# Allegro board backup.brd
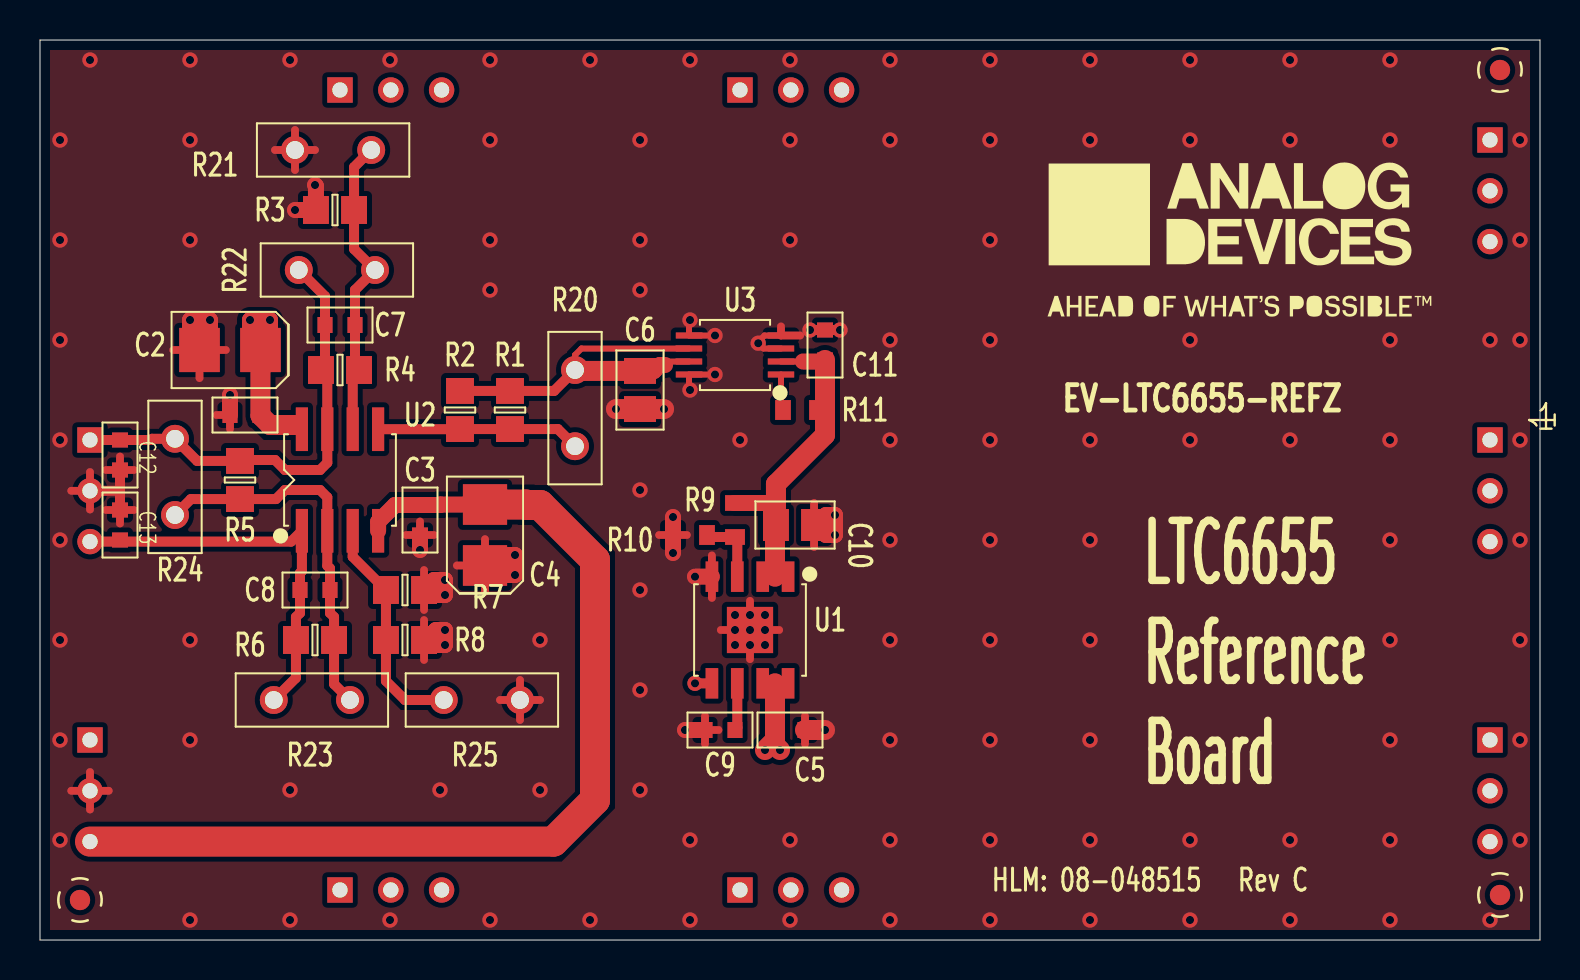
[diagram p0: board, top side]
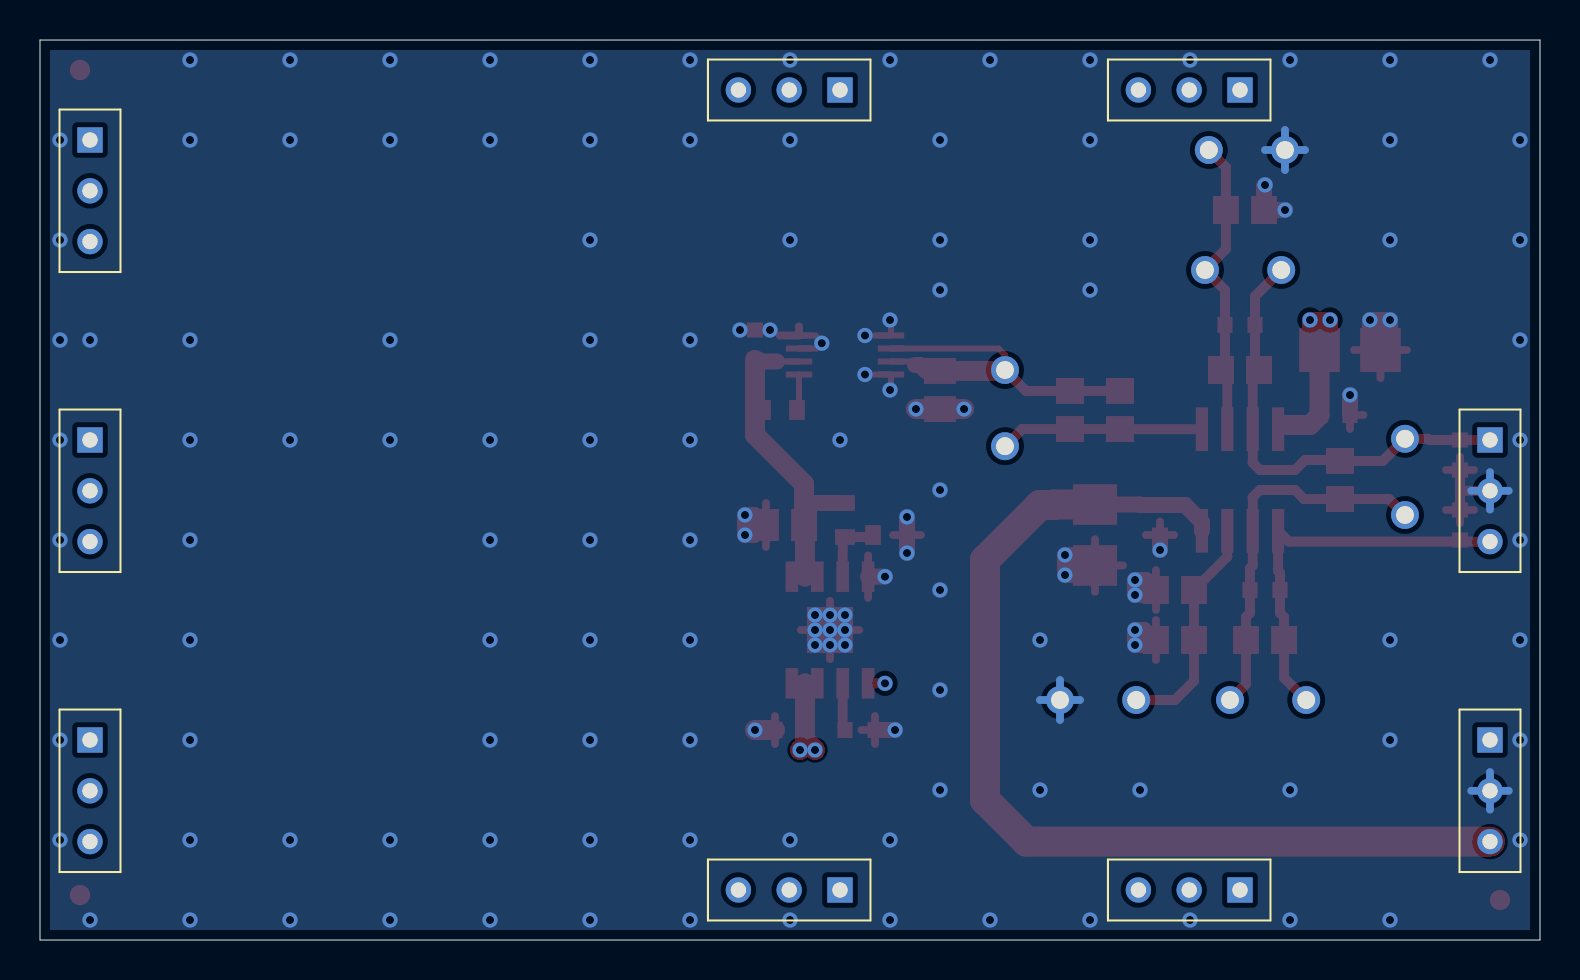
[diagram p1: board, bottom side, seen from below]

Outline 75 x 45 mm; copper layers: TOP, LAYER2, LAYER3, BOTTOM. Coordinates in mm from the lower left corner of the outline.
Outline path: 0,45 0,0 75,0 75,45 0,45

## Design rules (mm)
constraint set DEFAULT: min track width 0.19

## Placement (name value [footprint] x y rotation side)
C1  0.1UF  [C0603]  10.25 26.25 0 top
C2  10uF  [C3528]  9.5 29.5 180 top
C3  0.1UF  [C0603]  19 21 270 top
C4  10uF  [C3528]  22.25 20.25 90 top
C5  1uF  [C0603]  37.5 10.5 0 top
C6  10UF  [C0805H53]  30 27.5 270 top
C7  0.1UF  [C0603]  15 30.75 180 top
C8  0.1UF  [C0603]  13.75 17.5 180 top
C9  10000pF  [C0603]  34 10.5 180 top
C10  2.2UF  [C0805H53]  37.75 20.75 0 top
C11  0.1UF  [C0603]  39.25 29.75 90 top
C12  1UF  [C0603]  4 24.25 270 top
C13  1UF  [C0603]  4 20.75 270 top
J1  350-10-103-00-006000  [CNTHMHDR1X3L300W100H284]  2.5 10 270 bottom
J2  350-10-103-00-006000  [CNTHMHDR1X3L300W100H284]  35 42.5 0 bottom
J3  350-10-103-00-006000  [CNTHMHDR1X3L300W100H284]  15 42.5 0 bottom
J4  310-13-103-41-001000  [CNTHFHDR1X3L300W100H165]  2.5 25 270 bottom
J5  310-13-103-41-001000  [CNTHFHDR1X3L300W100H165]  72.5 40 270 bottom
J6  310-13-103-41-001000  [CNTHFHDR1X3L300W100H165]  15 2.5 0 bottom
J7  350-10-103-00-006000  [CNTHMHDR1X3L300W100H284]  35 2.5 0 bottom
J8  350-10-103-00-006000  [CNTHMHDR1X3L300W100H284]  72.5 10 270 bottom
J9  350-10-103-00-006000  [CNTHMHDR1X3L300W100H284]  72.5 25 270 bottom
NOREF  -  []  0 45 0 top
NOREF#2  -  [unnamed#2]  2 2 0 top
NOREF#3  -  []  -100 -95 0 top
NOREF#4  -  []  60 35 0 top
NOREF#5  -  []  36 14 0 top
NOREF#6  -  []  0 0 90 top
NOREF#7  -  [unnamed#2]  73 2.25 0 top
NOREF#8  -  []  -105 -95 0 top
NOREF#9  -  [unnamed#2]  73 43.5 0 top
NOREF#10  -  []  36.75 -16.25 0 top
R1  10K  [R0805]  23.5 26.5 270 top
R2  10K  [R0805]  21 26.5 270 top
R3  10K  [R0805]  14.75 36.5 0 top
R4  10K  [R0805]  15 28.5 180 top
R5  10K  [R0805]  10 23 90 top
R6  10K  [R0805]  13.75 15 180 top
R7  10K  [R0805]  18.25 17.5 180 top
R8  10K  [R0805]  18.25 15 180 top
R9  100K  [R0603]  34.75 21 270 top
R10  10K  [R0603]  32.5 20.25 180 top
R11  10K  [R0603]  38 26.5 180 top
R20  10K  [RRADTH150L300H336W105LD25]  26.75 28.5 270 top
R21  10K  [RRADTH150L300H336W105LD25]  12.75 39.5 0 top
R22  10K  [RRADTH150L300H336W105LD25]  16.75 33.5 180 top
R23  10K  [RRADTH150L300H336W105LD25]  15.5 12 180 top
R24  10K  [RRADTH150L300H336W105LD25]  6.75 21.25 90 top
R25  10K  [RRADTH150L300H336W105LD25]  24 12 180 top
U1  ADP7118ARDZ  [SO8NB-PAD2_3X2_3]  35.5 15.5 180 top
U2  ADA4077-2BRZ  [SO8]  15 23 0 top
U3  LTC6655BHMS8-5#PBF  [MSOP8]  34.75 29.25 90 top

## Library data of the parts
C1 C3 C7 C8 C11 = CAP: User Part Number: UPN; Tolerance: 10; alternate symbols: (); part number: CAP_SM-0.1UF,25V,10,E007204,C0603; tolerance: 10
C2 C4 = CAPP: User Part Number: UPN; Tolerance: N/A; alternate symbols: (); part number: CAPP_SM-10UF,N/A,N/A,E000695,C3528; tolerance: N/A
C5 = CAP: User Part Number: UPN; Tolerance: 10; alternate symbols: (); part number: CAP_SM-1UF,16V,10,E020596,C0603; tolerance: 10
C6 = CAP: Tolerance: 10; User Part Number: UPN; alternate symbols: (); part number: CAP_SM-10UF,10V,10,E023214,C0805H53; tolerance: 10
C9 = CAP: User Part Number: UPN; Tolerance: 10; alternate symbols: (); part number: CAP_SM-10000PF,50V,10,E015914,C0603; tolerance: 10
C10 = CAP: Tolerance: 10; User Part Number: UPN; alternate symbols: (); part number: CAP_SM-2.2UF,25V,10,E025703,C0805H53; tolerance: 10
C12 C13 = CAP: User Part Number: UPN; Tolerance: 10; alternate symbols: (); part number: CAP_SM-1UF,10V,10,E033698,C0603; tolerance: 10
J1-J3 J7-J9 = CN3P: User Part Number: UPN; Tolerance: N/A; alternate symbols: (); part number: CN3P_TH-350-10-103-00-006000,E027762,CNTHMHDR1X3L300W100H284; tolerance: N/A
J4-J6 = CN3P: User Part Number: UPN; Tolerance: N/A; alternate symbols: (); part number: CN3P_TH-310-13-103-41-001000,E027752,CNTHFHDR1X3L300W100H165; tolerance: N/A
R1-R8 = RES: User Part Number: UPN; Tolerance: 0.1; alternate symbols: (R0805L); part number: RES_SM-10K,E003806,1/8W,0.1,R0805; tolerance: 0.1
R9 = RES: User Part Number: UPN; Tolerance: 1; alternate symbols: (R0603L); part number: RES_SM-100K,E010279,1/10W,1,R0603; tolerance: 1
R10 R11 = RES: User Part Number: UPN; Tolerance: 1; alternate symbols: (R0603L); part number: RES_SM-10K,E003671,1/10W,1,R0603; tolerance: 1
R20-R25 = RES: Tolerance: 0.005; User Part Number: UPN; alternate symbols: (); part number: RES_TH-10K,E018578,6/10W,0.005,RRADTH150L300H336W105LD25; tolerance: 0.005
U1 = ADP7118_V3: Tolerance: N/A; User Part Number: UPN; alternate symbols: (); part number: ADP7118_V3_SM-ADP7118ARDZ,E020780,SO8NB-PAD2_3X2_3; tolerance: N/A
U2 = ADA4077_2: User Part Number: UPN; Tolerance: N/A; alternate symbols: (); part number: ADA4077_2_SM-ADA4077-2BRZ,E018506,SO8; tolerance: N/A
U3 = LINLTC6655: Tolerance: N/A; User Part Number: UPN; alternate symbols: (); part number: LINLTC6655_SM-LTC6655BHMS8-5#PBF,E020815,MSOP8; tolerance: N/A

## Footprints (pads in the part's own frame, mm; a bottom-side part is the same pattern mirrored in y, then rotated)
C0603
  rect 0.75x0.8 smd: 1(-0.75,0) 2(0.75,0)
C0805H53
  rect 1.295x1.6 smd: 1(-0.953,0) 2(0.953,0)
C3528
  rect 2.032x2.21 smd: N(1.524,0) P(-1.524,0)
CNTHFHDR1X3L300W100H165
  rect 1.27x1.27 hole 0.762: 1(0,0)
  round 1.27 hole 0.762: 2(2.54,0) 3(5.08,0)
CNTHMHDR1X3L300W100H284
  rect 1.27x1.27 hole 0.762: 1(0,0)
  round 1.27 hole 0.762: 2(2.54,0) 3(5.08,0)
MSOP8
  rect 0.305x1.321 smd: 1(-0.975,-2.3) 2(-0.325,-2.3) 3(0.325,-2.3) 4(0.975,-2.3) 5(0.975,2.3) 6(0.325,2.3) 7(-0.325,2.3) 8(-0.975,2.3)
R0603
  rect 0.787x0.991 smd: 1(-0.85,0) 2(0.85,0)
R0805
  rect 1.295x1.397 smd: 1(-0.953,0) 2(0.953,0)
RRADTH150L300H336W105LD25
  round 1.397 hole 0.889: 1(0,0) 2(3.81,0)
SO8
  rect 0.61x2.184 smd: 1(-1.905,-2.54) 2(-0.635,-2.54) 3(0.635,-2.54) 4(1.905,-2.54) 5(1.905,2.54) 6(0.635,2.54) 7(-0.635,2.54) 8(-1.905,2.54)
SO8NB-PAD2_3X2_3
  rect 0.635x1.524 smd: 1(-1.905,-2.667) 2(-0.635,-2.667) 3(0.635,-2.667) 4(1.905,-2.667) 5(1.905,2.667) 6(0.635,2.667) 7(-0.635,2.667) 8(-1.905,2.667)
  rect 2.311x2.311 smd: PAD(0,0)
unnamed#2
  round 1.016 smd: (0,0)

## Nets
AGND: C1.1 C2.N(N2) C3.2(N2) C4.P C5.2(N2) C6.2(N2) C9.2(N2) C10.2(N2) C11.2(N2) C12.2(N2) C13.1 J1.2 J4.2 R3.1 R7.1 R8.1 R10.2(N2) R21.1 R25.1 U1.4 U1.PAD U3.3 U3.4 U3.5 U3.8
VDD: C1.2(N2) C2.P C5.1 J1.1 U1.5 U1.7 U1.8 U2.8
VSS: C3.1 C4.N(N2) J1.3(N3) U2.4(V-)
UNNAMED_2_ADA40772_I74_: C7.1 R3.2(N2) R4.1 R21.2(N2) R22.1 U2.6
UNNAMED_2_ADA40772_I74__1: R1.2(N2) R2.2(N2) R20.2(N2) U2.5
UNNAMED_2_ADA40772_I75_: C8.1 R5.1 R6.1 R23.1 R24.1 U2.2
UNNAMED_2_ADA40772_I75__1: R7.2(N2) R8.2(N2) R25.2(N2) U2.3
UNNAMED_2_ADP7118V3_I79_SENSE: R9.2(N2) R10.1 U1.3
UNNAMED_2_ADP7118V3_I79_SS: C9.1 U1.6
UNNAMED_2_ADP7118V3_I79_VOUT1: C10.1 C11.1 R9.1 R11.1 U1.1 U1.2(VOUT2) U3.2
UNNAMED_2_CAP_I32_N1: C6.1 R1.1 R2.1 R20.1 U3.6(VOUT_S) U3.7
UNNAMED_2_LINLTC6655_I78_SHDNN: R11.2(N2) U3.1
VREFN: C8.2(N2) C13.2(N2) J4.3(N3) R6.2(N2) R23.2(N2) U2.1
VREFP: C7.2(N2) C12.1 J4.1 R4.2(N2) R5.2(N2) R22.2(N2) R24.2(N2) U2.7

Pads without a net: J2 1 2 3; J3 1 2 3; J5 1 2 3; J6 1 2 3; J7 1 2 3; J8 1 2 3; J9 1 2 3

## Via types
v1: diameter 0.762, hole 0.406, TOP to BOTTOM, 145 vias

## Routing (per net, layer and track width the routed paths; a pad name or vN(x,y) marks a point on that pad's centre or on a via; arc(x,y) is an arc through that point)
AGND: length 357.9
  TOP w0.3: v1(35.5,15.5) v1(34.75,16.25) ; v1(32.5,27.5) 32.45,27.55 U3.8 v1(33.75,28.27) ; U3.4 36.23,30.23 35.91,29.91 v1(35.91,29.84) 36.17,29.57 U3.3 ; v1(32.5,31) 32.45,30.95 U3.5 v1(33.75,30.23)
  TOP w0.39: J4.2 2.5,23.4 ; J4.2 2.5,21.52 ; J4.2 1.56,22.46 ; 38.7,21.85 C10.2 38.7,19.65 ; C13.1 4.7,21.5 ; C13.1 4,20.82 ; C13.1 3.3,21.5 ; C4.P 23.66,18.73 ; C4.P 22.25,17.41 ; C4.P 20.84,18.73 ; C4.P 22.25,20.04 ; R7.1 20.15,17.5 ; R7.1 19.2,16.5 ; R7.1 19.2,18.5 ; C9.2 33.93,10.5 ; C9.2 33.25,9.8 ; C9.2 33.25,11.2 ; 38.25,9.8 C5.2 38.25,11.2 ; 3.3,23.5 C12.2 ; C12.2 4,24.18 ; C12.2 4.7,23.5 ; 19.2,14 R8.1 19.2,16 ; 38.01,30.23 U3.4 37.05,30.68 ; R25.1 24,13 ; R25.1 25,12 ; R25.1 24,11 ; R25.1 23,12 ; 30.96,20.25 R10.2 32.34,20.25 ; 12.75,38.5 R21.1 ; R21.1 13.75,39.5 ; R21.1 11.75,39.5 ; R21.1 12.75,40.5 ; v1(35.5,15.5) 36.96,15.5 ; v1(35.5,15.5) 35.5,14.04 ; v1(35.5,15.5) 35.5,16.96 ; v1(35.5,15.5) 34.04,15.5 ; 1.56,7.46 J1.2 ; J1.2 3.44,7.46 ; J1.2 2.5,8.4 ; J1.2 2.5,6.52 ; 18.3,20.25 C3.2 ; C3.2 19,20.93 ; C3.2 19.7,20.25 ; 8.82,26.25 C1.1 9.5,25.55 ; 33.59,17.1 U1.4 33.59,19.23 ; 6.66,29.5 C2.N ; C2.N 9.29,29.5 ; C2.N 7.98,28.09
  TOP w0.5: 4,22.41 3.95,22.46 J4.2 ; 4,22.41 C12.2 ; 4,22.41 C13.1 ; v1(40,30.5) C11.2 v1(38.5,30.5)
  TOP w0.8: C10.2 39.25,20.75 ; 39.25,20.75 39.25,21.2 39.3,21.25 v1(39.75,21.25) v1(39.75,20.25) 39.3,20.25 39.25,20.3 39.25,20.75 ; C3.2 v1(19,19.5) ; R8.1 19.75,15 ; 19.75,15 19.75,15.45 19.8,15.5 v1(20.25,15.5) v1(20.25,14.75) 19.8,14.75 19.75,14.8 19.75,15 ; C2.N 7.98,30.48 ; 7.98,30.48 7.55,30.48 7.5,30.53 v1(7.5,31) v1(8.5,31) 8.5,30.53 8.45,30.48 7.98,30.48 ; C9.2 v1(32.25,10.5) ; C1.1 v1(9.5,27.25) ; v1(31.65,21.15) R10.2 v1(31.65,19.35) ; U1.4 v1(32.75,18.17) ; v1(12.75,36.5) R3.1 13.8,37.7 v1(13.75,37.75) ; 19.45,17.25 v1(20.25,17.25) v1(20.25,18) 19.7,18 R7.1 19.45,17.25 ; 22.77,19.25 C4.P 22.73,18.25 v1(23.75,18.25) v1(23.75,19.25) 22.77,19.25
  TOP w1: v1(28.8,26.55) C6.2 v1(31.2,26.55) ; C5.2 v1(39.25,10.5)
  LAYER2 w0.39: 1.56,22.46 J4.2 ; J4.2 2.5,21.52 ; J4.2 2.5,23.4 ; J4.2 3.44,22.46 ; R25.1 25,12 ; R25.1 24,11 ; R25.1 23,12 ; R25.1 24,13 ; 1.56,7.46 J1.2 ; J1.2 3.44,7.46 ; J1.2 2.5,8.4 ; J1.2 2.5,6.52 ; 11.75,39.5 R21.1 ; R21.1 12.75,38.5 ; R21.1 13.75,39.5 ; R21.1 12.75,40.5
  LAYER3 w1: v1(27.5,1) v1(22.5,1) v1(17.5,1) v1(12.5,1) v1(7.5,1) 1.05,1 1,1.05 v1(1,5) v1(1,10) v1(1,15) v1(1,20) v1(1,25) v1(1,30) v1(1,35) v1(1,40) 1,43.95 1.05,44 v1(2.5,44) v1(7.5,44) v1(12.5,44) v1(17.5,44) v1(22.5,44) v1(27.5,44) v1(32.5,44) v1(37.5,44) v1(42.5,44) v1(47.5,44) v1(52.5,44) v1(57.5,44) v1(62.5,44) v1(67.5,44) 73.95,44 74,43.95 v1(74,40) v1(74,35) v1(74,30) v1(74,25) v1(74,20) v1(74,15) v1(74,10) v1(74,5) 74,1.05 73.95,1 v1(72.5,1) v1(67.5,1) v1(62.5,1) v1(57.5,1) v1(52.5,1) v1(47.5,1) v1(42.5,1) v1(37.5,1) v1(32.5,1) v1(27.5,1)
  BOTTOM w0.39: 2.5,21.52 J4.2 ; J4.2 1.56,22.46 ; J4.2 2.5,23.4 ; J4.2 3.44,22.46 ; 2.5,6.52 J1.2 ; J1.2 3.44,7.46 ; J1.2 2.5,8.4 ; J1.2 1.56,7.46 ; 23,12 R25.1 ; R25.1 24,13 ; R25.1 25,12 ; R25.1 24,11 ; 12.75,38.5 R21.1 ; R21.1 11.75,39.5 ; R21.1 12.75,40.5 ; R21.1 13.75,39.5
  vias: v1(7.5,40) v1(7.5,35) v1(7.5,15) v1(7.5,10) v1(12.5,7.5) v1(20,7.5) v1(22.5,40) v1(22.5,35) v1(22.5,32.5) v1(25,15) v1(25,7.5) v1(30,40) v1(30,35) v1(30,32.5) v1(30,22.5) v1(30,17.5) v1(30,12.5) v1(30,7.5) v1(32.5,5) v1(34.75,15.5) v1(34.75,14.75) v1(35,25) v1(35.5,16.25) v1(35.5,14.75) v1(36.25,16.25) v1(36.25,15.5) v1(36.25,14.75) v1(37.5,40) v1(37.5,35) v1(37.5,5) v1(42.5,40) v1(42.5,30) v1(42.5,25) v1(42.5,20) v1(42.5,15) v1(42.5,10) v1(42.5,5) v1(47.5,40) v1(47.5,35) v1(47.5,30) v1(47.5,25) v1(47.5,20) v1(47.5,15) v1(47.5,10) v1(47.5,5) v1(52.5,40) v1(52.5,25) v1(52.5,20) v1(52.5,15) v1(52.5,10) v1(52.5,5) v1(57.5,40) v1(57.5,30) v1(57.5,25) v1(57.5,5) v1(62.5,40) v1(62.5,25) v1(62.5,5) v1(67.5,40) v1(67.5,30) v1(67.5,25) v1(67.5,20) v1(67.5,15) v1(67.5,10) v1(67.5,5) v1(72.5,30)
VDD: length 18.8
  TOP w0.3: C1.2 11.02,26.23 ; U2.8 12.96,25.54 12.75,25.75
  TOP w0.5: U1.7 U1.8 ; U1.5 v1(32.75,12.83)
  TOP w0.8: 11.19,29.94 11.5,30.25 v1(11.5,31) v1(10.5,31) 10.5,30.62 11.19,29.94 ; 11.19,29.94 11.19,29.66 C2.P
  TOP w1: 36.75,10 36.75,9.75 v1(37,9.5) ; 36.75,10 C5.1 36.75,12.83 ; 36.75,10 v1(36.25,9.5) ; 12.75,25.75 11.5,25.75 11.02,26.23 C2.P
  LAYER3 w0.39: 2.5,9.06 J1.1 ; J1.1 3.44,10 ; J1.1 2.5,10.94
VSS: length 50.9
  TOP w0.8: C4.N 20.02,21.77 20,21.75 C3.1 17.75,21.75 16.91,20.91 U2.4
  TOP w1.5: J1.3 25.67,4.92 27.75,7 27.75,19 25,21.75 24.33,21.75 24.3,21.77 C4.N
UNNAMED_2_ADA40772_I74_: length 15.4
  TOP w0.5: R21.2 15.7,38.64 R3.2 15.7,34.55 R22.1 15.75,32.5 C7.1 15.75,28.7 R4.1 15.63,28.18 U2.6
UNNAMED_2_ADA40772_I74__1: length 10.2
  TOP w0.5: R20.2 25.89,25.55 R1.2 R2.2 20.99,25.54 U2.5
UNNAMED_2_ADA40772_I75_: length 18.9
  TOP w0.5: R24.1 7.55,22.05 R5.1 11.8,22.05 12.25,22.5 14,22.5 14.37,22.14 U2.2 14.37,18.71 14.5,18.58 C8.1 14.5,16.35 14.7,16.15 R6.1 14.7,12.8 R23.1
UNNAMED_2_ADA40772_I75__1: length 11.5
  TOP w0.5: U2.3 15.63,19.16 R7.2 R8.2 17.3,12.95 18.25,12 R25.2
UNNAMED_2_ADP7118V3_I79_SENSE: length 3.5
  TOP w0.5: U1.3 34.87,20.04 R9.2 33.45,20.15 R10.1
UNNAMED_2_ADP7118V3_I79_SS: length 2.4
  TOP w0.5: C9.1 34.87,10.62 U1.6
UNNAMED_2_ADP7118V3_I79_VOUT1: length 17.9
  TOP w0.3: R11.1 39.25,26.5 ; 38.15,28.93 U3.2
  TOP w0.5: U1.2 U1.1 ; C10.1 36.75,20.7
  TOP w0.8: R9.1 36.7,21.85 36.8,21.75 ; 38.15,28.93 39.17,28.93 C11.1
  TOP w1: 36.75,20.7 36.75,18.17 ; C11.1 39.25,25.25 36.8,22.8 C10.1
UNNAMED_2_CAP_I32_N1: length 18.7
  TOP w0.3: U3.6 27.07,29.57 26.75,29.25 R20.1 ; U3.7 31.43,28.93 31.25,28.75
  TOP w0.5: R2.1 R1.1 25.7,27.45 R20.1
  TOP w0.8: C6.1 30.7,28.45 31,28.75 31.25,28.75
  TOP w1: R20.1 26.8,28.45 C6.1
UNNAMED_2_LINLTC6655_I78_SHDNN: length 1.8
  TOP w0.3: U3.1 37.05,26.6 R11.2
VREFN: length 19.9
  TOP w0.5: 4,19.92 12.55,19.92 U2.1 13.1,18.45 13,18.35 C8.2 13,16.35 12.8,16.15 R6.2 12.8,13.11 R23.2 ; 4,19.92 J4.3 ; 4,19.92 C13.2
VREFP: length 23.1
  TOP w0.5: J4.1 C12.1 5.54,25 5.6,25.06 R24.2 7.86,23.95 R5.2 10.05,24 11.75,24 12.25,23.5 14,23.5 14.37,23.86 U2.7 14.37,28.18 R4.2 14.25,28.7 C7.2 14.25,32.19 R22.2

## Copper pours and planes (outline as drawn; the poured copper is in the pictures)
AGND on TOP, BOTTOM, LAYER2: 0.5,44.5 0.5,0.5 74.5,0.5 74.5,44.5
VDD on LAYER3: 0.5,44.5 0.5,0.5 74.5,0.5 74.5,44.5

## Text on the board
Ref Des/Silkscreen Top: HLM: 08-048515   Rev C | EV-LTC6655-REFZ | LTC6655 | Reference | Board
LAYER2: L2 Internal GND | 08-      -07
LAYER3: L3 Internal PWR | 08-      -08
XSECTION_CHART: Primary Side Silkscreen | Primary Side Soldermask | 0.035 (1oz) Copper Plating | Primary side 0.017 (0.5oz) Copper Foil | FR4 Prepreg | 0.035 (1oz) Copper | Secondary Side 0.017 (0.5oz) Copper Foil | FR4 CORE | Secondary Side Soldermask | Secondary side Silkscreen | 1.6mm +/-10% | 4 LAYER STACKUP
DIMENSION: Fill with non conductive epoxy | and overplate.
User.20: ECR-079883 | 06/03/18 | E.SANZ | B | LTC6655 REFERENCE BRD
User.23: 10. Manufacturer UL and Date codes on the bottom side silkscreen as indicated. | 1. Material: 4 Layer FR4 glass epoxy laminate 1.6mm +/- 10%. material to be RoHS compliant. | 2. Plated thru holes and conductive pattern electroplated with 0.255mm min. thick copper. | 3. Processing tolerence: | 4. Warp and twist within 0.1875mm per 25mm (0.75%) | 5. Dimensions are for the finished part. | 6. SOLDERMASK: liquid Photo Imeagable soldermask over bare copper (SMOBC), | 7. SCREENING: Screen component outlines and nomenclature using indelible white ink on both sides. | 8. Electrically test 100%. | 9. Break all sharp edges 0.35mm Radius max. | Board to be fabricated per IPC-6012A, CLASS 2. | Terminal areas and plated thru holes to be ENIG plated. | colour GREEN both sides using the pattern provided. No mask is permitted on the terminal areas. | Soldermask to etch registration within 0.125mm total. | A. Conductive pattern front to back registration within 0.125mm total. | B. Minimum annual ring surrounding holes 0.05mm. | C. Finished conductive pattern to be within 0.05mm of true size. | D. Minimumfeature size 0.2mm | E. Minimum air gap 0.12mm | Nomenclature shall be legible. Screen to etch registration within 0.15mm total. | FABRICATION NOTES: | 1 | FABRICATION | 09-048515-01 | C
